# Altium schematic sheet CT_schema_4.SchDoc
size 469 x 410 mm
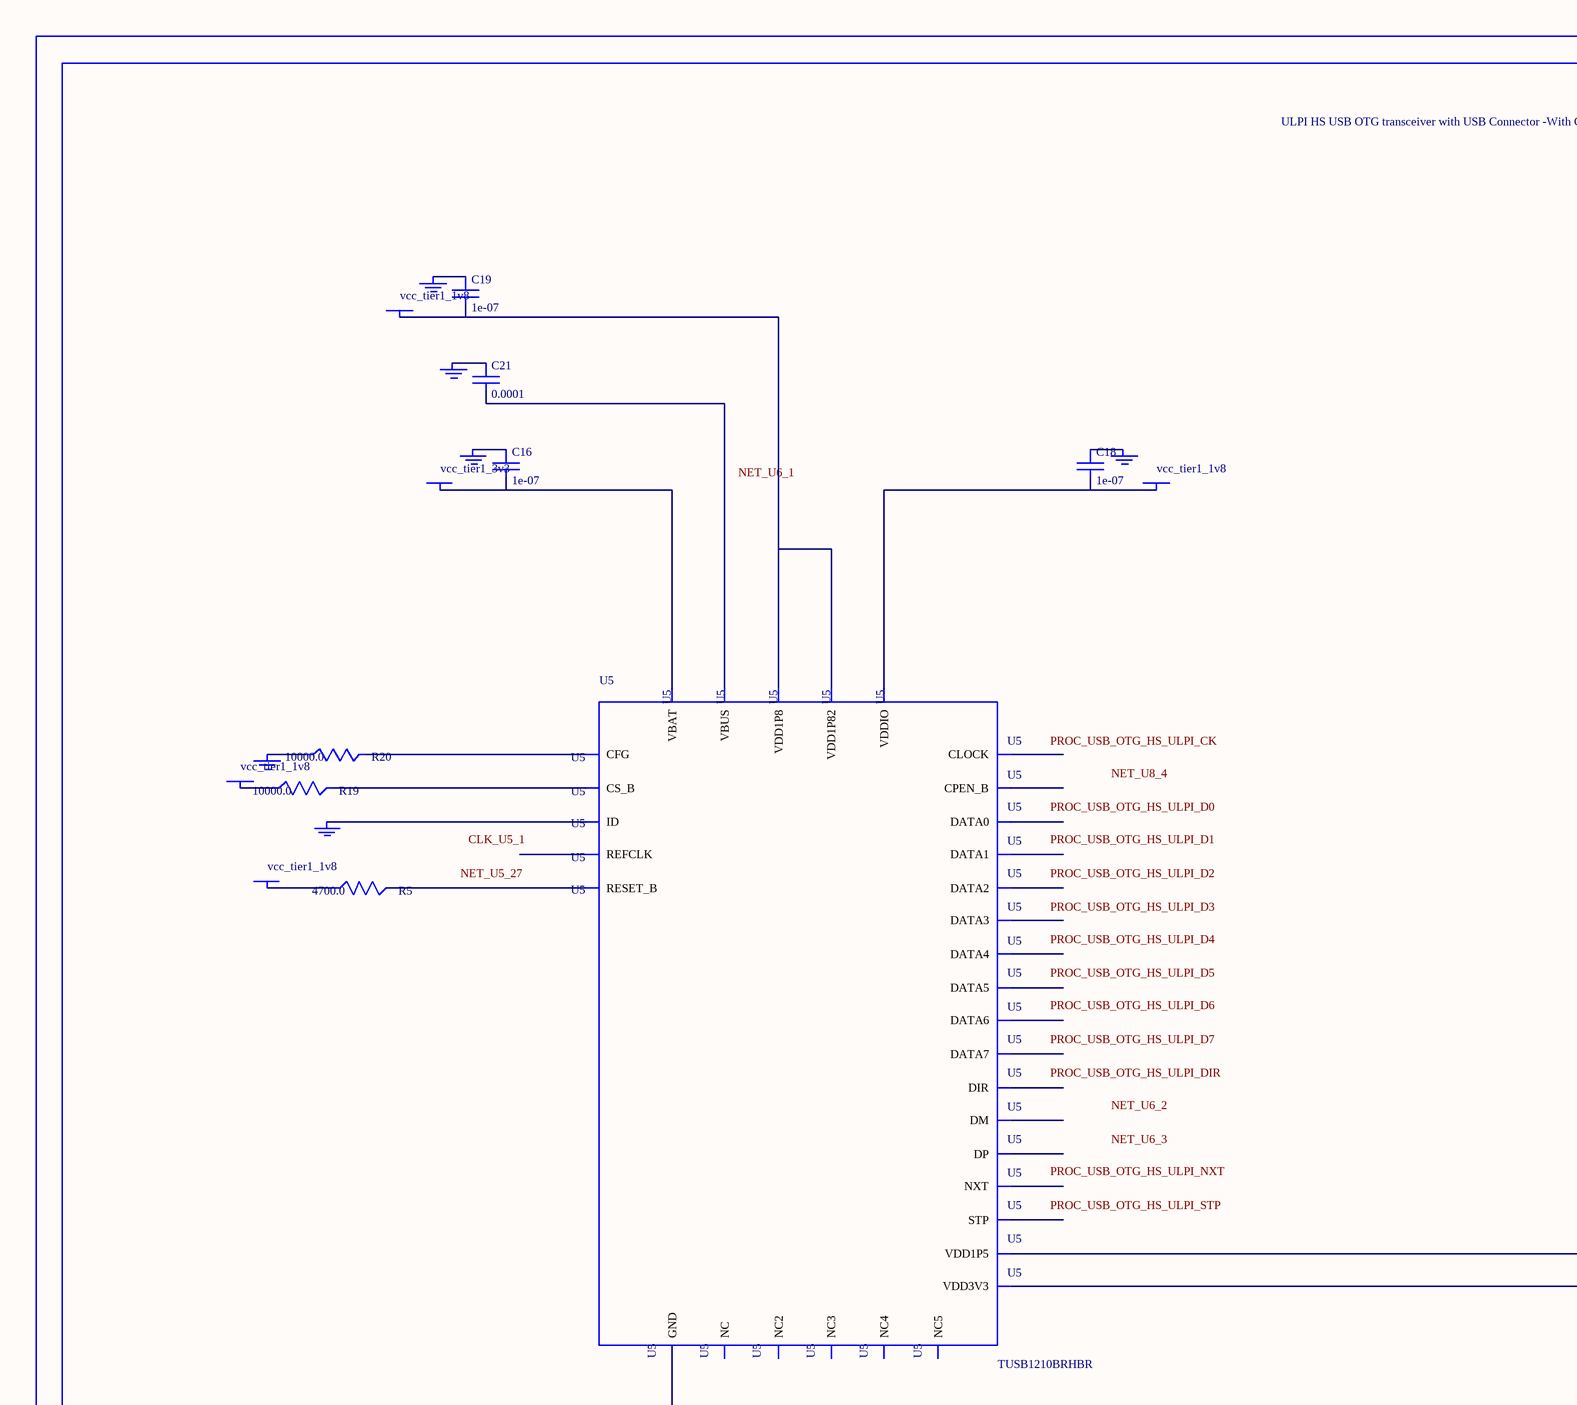
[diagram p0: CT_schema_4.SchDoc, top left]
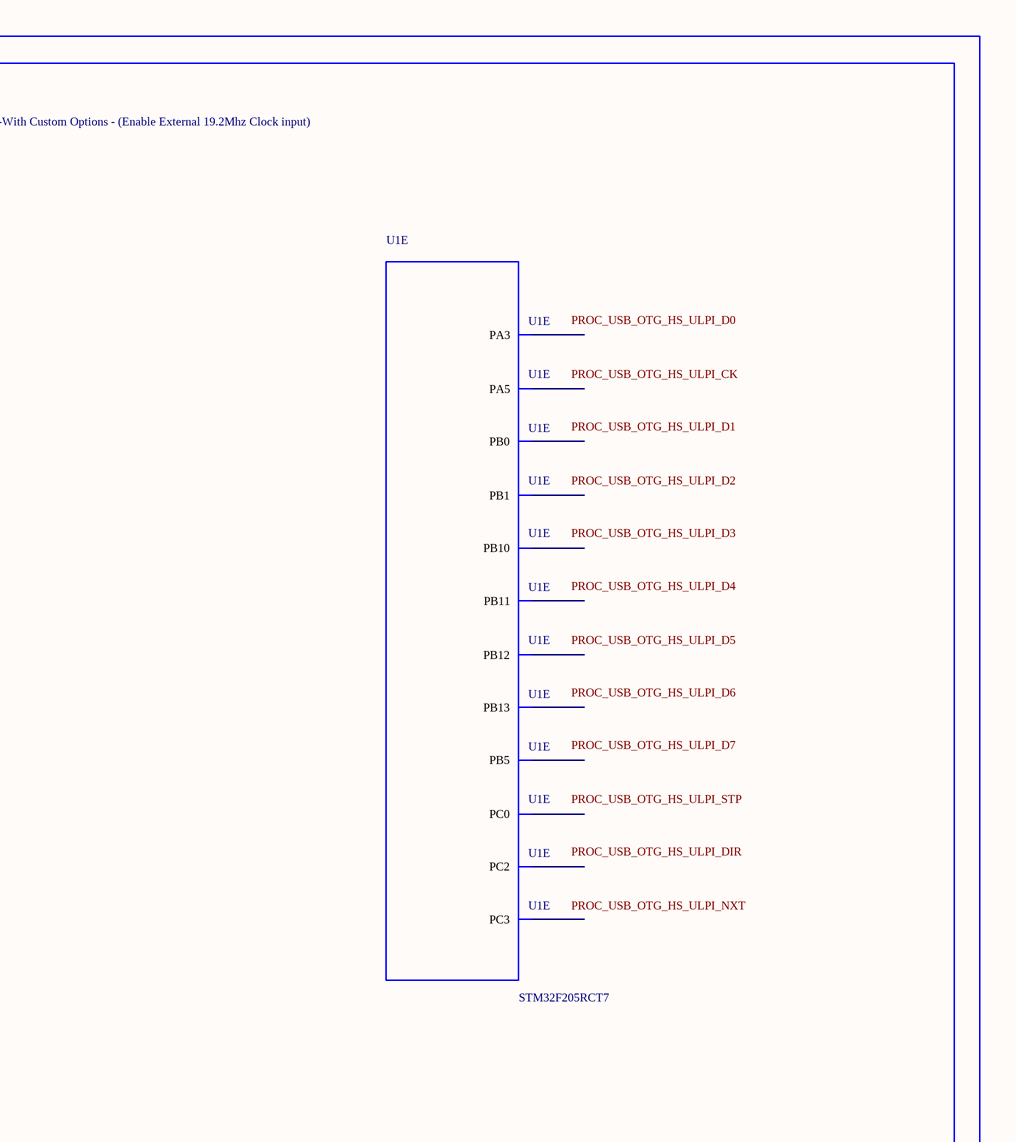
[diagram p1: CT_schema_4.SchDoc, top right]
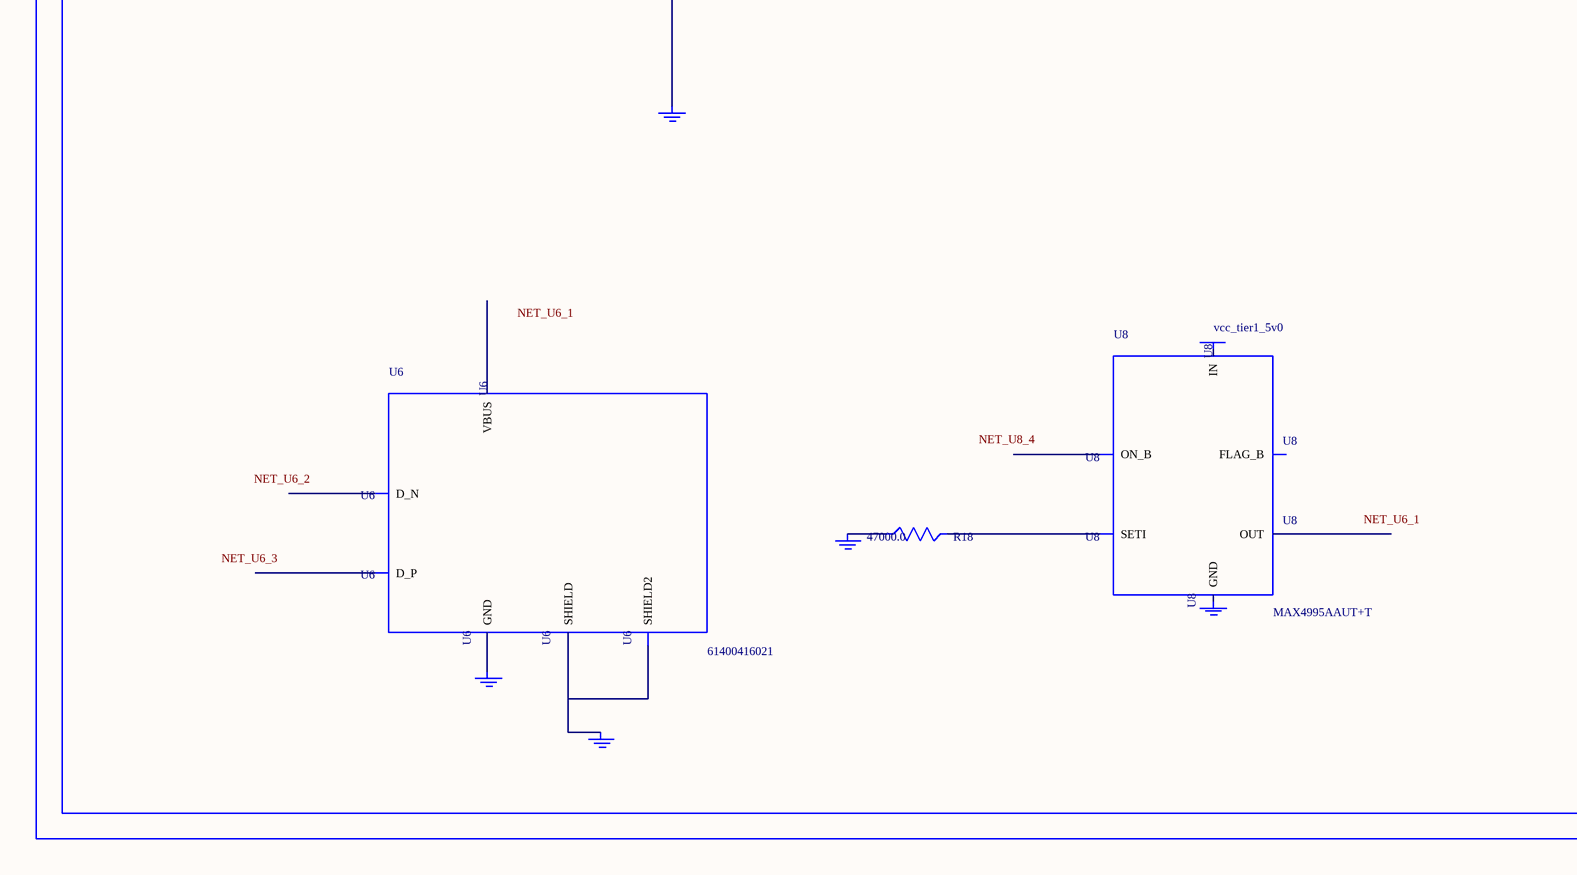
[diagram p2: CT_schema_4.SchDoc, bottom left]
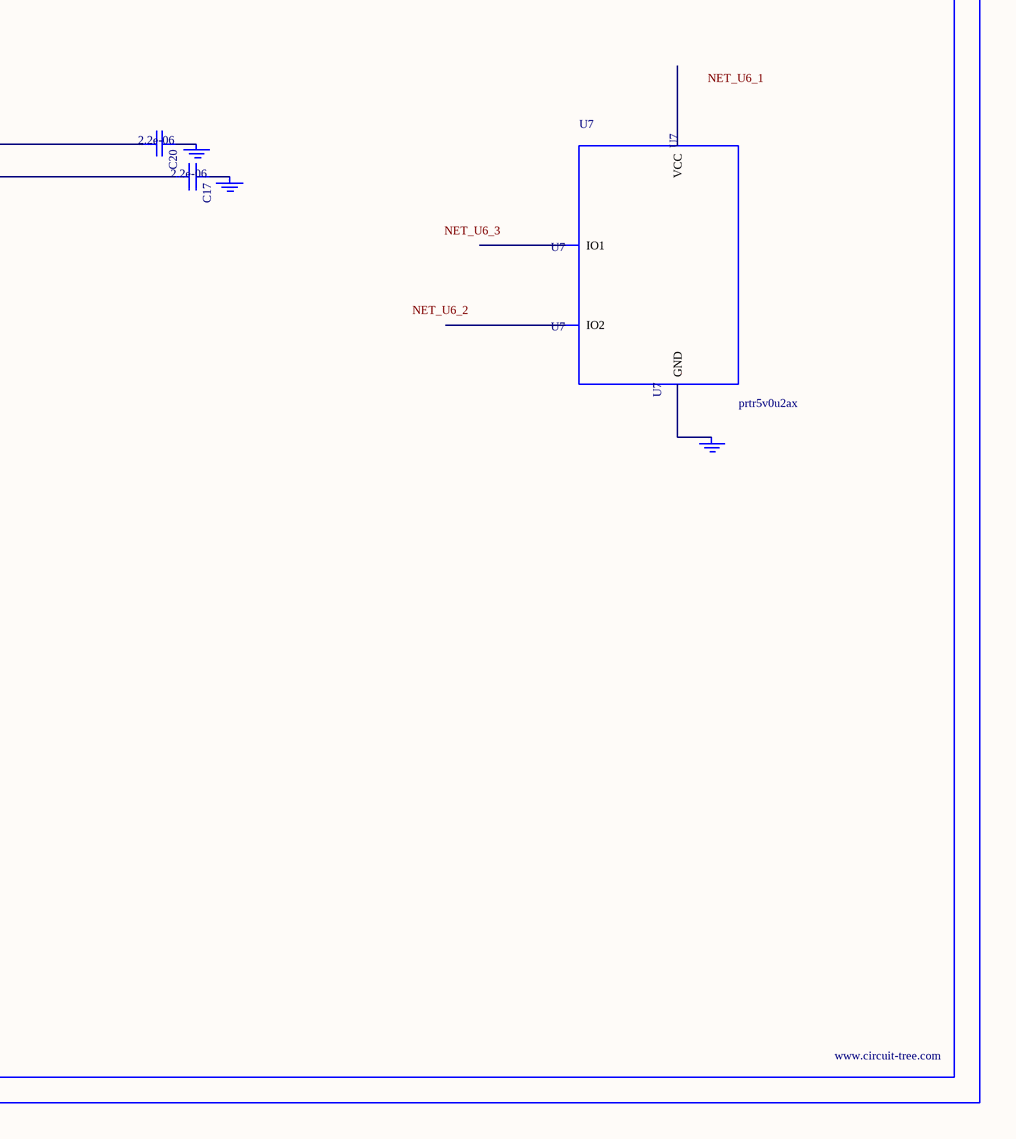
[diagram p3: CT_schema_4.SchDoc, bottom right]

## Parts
BORDER3  (no value)
C16  1e-07  [C0402]
C17  2.2e-06  [C0603]
C18  1e-07  [C0402]
C19  1e-07  [C0402]
C20  2.2e-06  [C0603]
C21  0.0001  [R0603]
GND_INSTANCE_3_0  (no value)
GND_INSTANCE_3_1  (no value)
GND_INSTANCE_3_2  (no value)
GND_INSTANCE_3_3  (no value)
GND_INSTANCE_3_4  (no value)
GND_INSTANCE_3_5  (no value)
GND_INSTANCE_3_6  (no value)
GND_INSTANCE_3_7  (no value)
GND_INSTANCE_3_8  (no value)
GND_INSTANCE_3_9  (no value)
GND_INSTANCE_3_10  (no value)
GND_INSTANCE_3_11  (no value)
GND_INSTANCE_3_12  (no value)
GND_INSTANCE_3_13  (no value)
POWER_INSTANCE_3_0  vcc_tier1_1v8
POWER_INSTANCE_3_1  vcc_tier1_3v3
POWER_INSTANCE_3_2  vcc_tier1_1v8
POWER_INSTANCE_3_3  vcc_tier1_1v8
POWER_INSTANCE_3_4  vcc_tier1_1v8
POWER_INSTANCE_3_5  vcc_tier1_5v0
R5  4700.0  [R0603]
R18  47000.0  [R0603]
R19  10000.0  [R0603]
R20  10000.0  [R0603]
U1  STM32F205RCT7  [LQFP64]  (part E of 7)
U5  TUSB1210BRHBR  [RHB32_3P45X3P45]
U6  61400416021  [USB-A-H]
U7  prtr5v0u2ax  [SOT143B]
U8  MAX4995AAUT+T  [SOT-23-6]

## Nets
NetC16_1: C16.1 GND_INSTANCE_3_3.0(GND)
NetC16_2: C16.2 POWER_INSTANCE_3_1.0(PWR) U5.21(VBAT)
NetC17_1: C17.1 GND_INSTANCE_3_2.0(GND)
NetC17_2: C17.2 U5.20(VDD3V3)
NetC18_1: C18.1 GND_INSTANCE_3_7.0(GND)
NetC18_2: C18.2 POWER_INSTANCE_3_3.0(PWR) U5.32(VDDIO)
NetC19_1: C19.1 GND_INSTANCE_3_6.0(GND)
NetC19_2: C19.2 POWER_INSTANCE_3_2.0(PWR) U5.28(VDD1P8) U5.30(VDD1P82)
NetC20_1: C20.1 GND_INSTANCE_3_0.0(GND)
NetC20_2: C20.2 U5.12(VDD1P5)
NetC21_1: C21.1 GND_INSTANCE_3_4.0(GND)
NetC21_2: C21.2 U5.22(VBUS)
NetGND_INSTANCE_3_1_0: GND_INSTANCE_3_1.0(GND) R20.1
NetGND_INSTANCE_3_5_0: GND_INSTANCE_3_5.0(GND) U5.23(ID)
NetGND_INSTANCE_3_8_0: GND_INSTANCE_3_8.0(GND) U5.33(GND)
NetGND_INSTANCE_3_9_0: GND_INSTANCE_3_9.0(GND) U6.5(SHIELD) U6.6(SHIELD2)
NetGND_INSTANCE_3_10_0: GND_INSTANCE_3_10.0(GND) U6.4(GND)
NetGND_INSTANCE_3_11_0: GND_INSTANCE_3_11.0(GND) U7.1(GND)
NetGND_INSTANCE_3_12_0: GND_INSTANCE_3_12.0(GND) R18.1
NetPOWER_INSTANCE_3_0_0: POWER_INSTANCE_3_0.0(PWR) R19.1
NetPOWER_INSTANCE_3_4_0: POWER_INSTANCE_3_4.0(PWR) R5.1
NetR5_2: R5.2 U5.27(RESET_B)
NetR18_2: R18.2 U8.3(SETI)
NetR19_2: R19.2 U5.11(CS_B)
NetR20_2: R20.2 U5.14(CFG)

Not connected (* = marked no-connect by the designer): GND_INSTANCE_3_13 0(GND); POWER_INSTANCE_3_5 0(PWR); U1 8(PC0) 10(PC2) 11(PC3) 17(PA3) 21(PA5) 26(PB0) 27(PB1) 29(PB10) 30(PB11) 33(PB12) 34(PB13) 57(PB5); U5 1(REFCLK) 2(NXT) 3(DATA0) 4(DATA1) 5(DATA2) 6(DATA3) 7(DATA4) 8(NC) 9(DATA5) 10(DATA6) 13(DATA7) 15(NC2) 16(NC3) 17(CPEN_B) 18(DP) 19(DM) 24(NC4) 25(NC5) 26(CLOCK) 29(STP) 31(DIR); U6 1(VBUS) 2(D_N) 3(D_P); U7 2(IO1) 3(IO2) 4(VCC); U8 1(OUT) 2(GND) 4(ON_B) 5(IN) 6(FLAG_B)

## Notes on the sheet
- Labels drawn without touching a wire or pin: CLK_U5_1, NET_U5_27, NET_U6_1, NET_U6_2, NET_U6_3, NET_U8_4, PROC_USB_OTG_HS_ULPI_CK, PROC_USB_OTG_HS_ULPI_D0, PROC_USB_OTG_HS_ULPI_D1, PROC_USB_OTG_HS_ULPI_D2, PROC_USB_OTG_HS_ULPI_D3, PROC_USB_OTG_HS_ULPI_D4, PROC_USB_OTG_HS_ULPI_D5, PROC_USB_OTG_HS_ULPI_D6, PROC_USB_OTG_HS_ULPI_D7, PROC_USB_OTG_HS_ULPI_DIR, PROC_USB_OTG_HS_ULPI_NXT, PROC_USB_OTG_HS_ULPI_STP

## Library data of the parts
BORDER3 = BORDER_PAGE3
C16 C18 C19 = C0402C104K3RACTU
C17 C20 = C0603C225K8RACTU
C21 = C21
GND_INSTANCE_3_0-GND_INSTANCE_3_13 = GND
POWER_INSTANCE_3_0-POWER_INSTANCE_3_5 = PWR
R5 = RC0603JR-074K7L
R18 = RC0603JR-0747KL
R19 R20 = RC0603JR-0710KL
